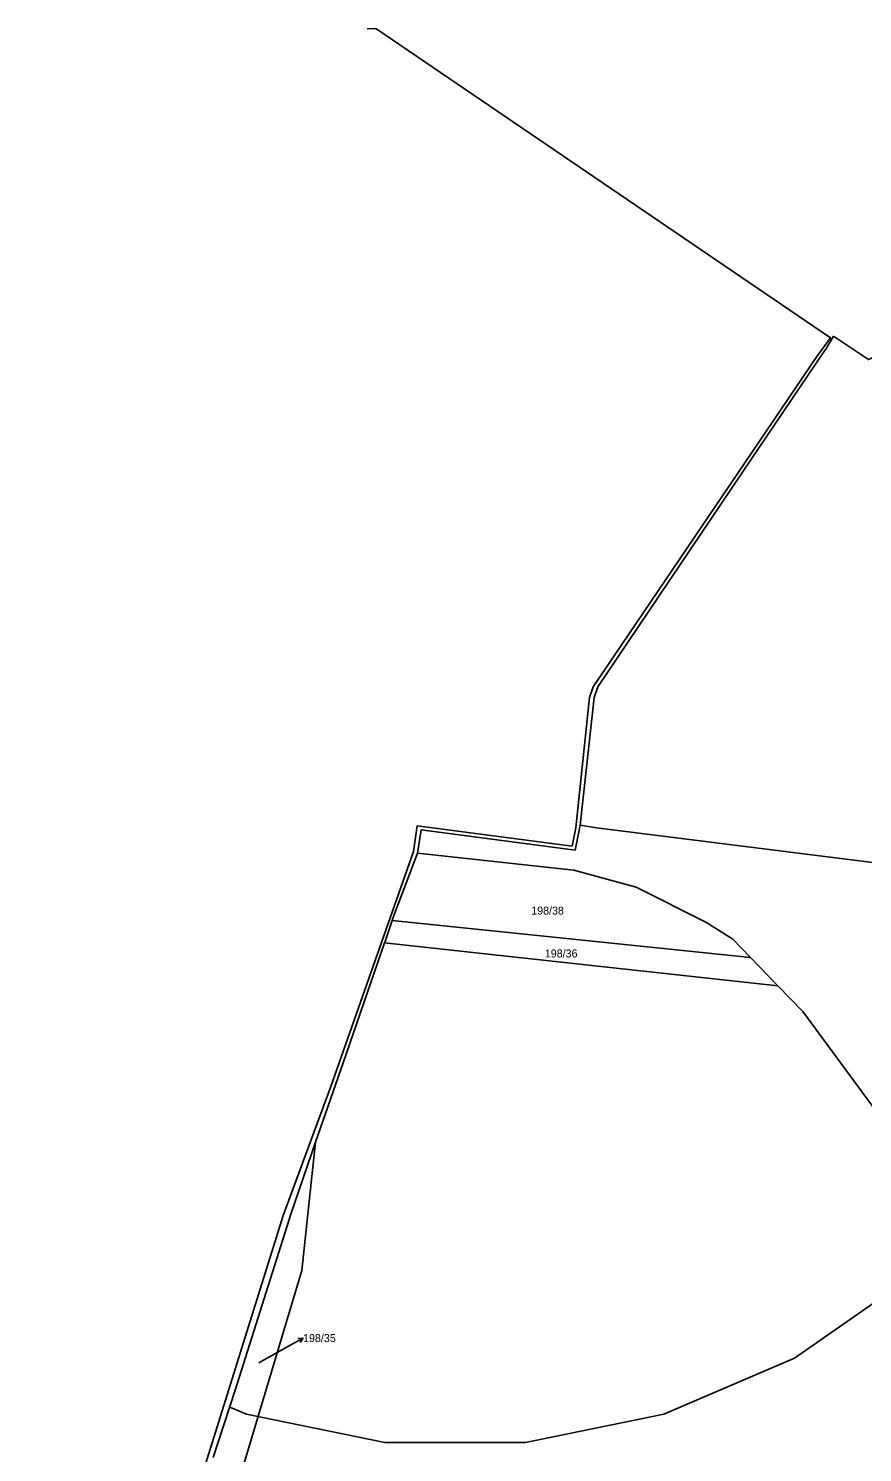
# Model space of a CAD drawing. Extents: x -882150 to -879379, y -1022570 to -1019819.
# Drawn here: x -880661.6 to -880484.4, y -1020201.6 to -1019899.2 of the extents above; entities that cross this region are included whole.
import ezdxf

# ---------------------------------------------------------------- set-up
doc = ezdxf.new("R2010")
doc.units = 0
for name, color, linetype in [('Hranice parcel', 7, 'Continuous'), ('Parcelní čísla', 7, 'Continuous'), ('Pop  PČ popisy', 7, 'Continuous'), ('Vnitřní kresba', 7, 'Continuous')]:
    doc.layers.add(name, color=color, linetype=linetype)

msp = doc.modelspace()

# ---------------------------------------------------------------- linework, layer by layer
at = {"layer": 'Hranice parcel'}
for p, q in [((-880492.18, -1019967.31), (-880490.55, -1019964.56)), ((-880492.57, -1019967.89), (-880492.18, -1019967.31)), ((-880541.4, -1020041.3), (-880540.65, -1020039.03)), ((-880544.4, -1020068.4), (-880541.4, -1020041.3)), ((-880578.19, -1020069.39), (-880578.97, -1020074.33)), ((-880578.19, -1020069.39), (-880545.46, -1020073.69)), ((-880545.46, -1020073.69), (-880544.4, -1020068.4)), ((-880540.91, -1020069), (-880544.4, -1020068.4)), ((-880584.03, -1020087.77), (-880578.97, -1020074.33)), ((-880584.03, -1020087.77), (-880584.33, -1020088.63)), ((-880584.33, -1020088.63), (-880585.79, -1020092.88)), ((-880508.2, -1020096.48), (-880584.33, -1020088.63)), ((-880594.78, -1020118.91), (-880585.96, -1020093.38)), ((-880585.79, -1020092.88), (-880585.96, -1020093.38)), ((-880585.96, -1020093.38), (-880502.38, -1020102.49)), ((-880502.38, -1020102.49), (-880508.2, -1020096.48)), ((-880594.78, -1020118.91), (-880600.6, -1020135.76))]:
    msp.add_line(p, q, dxfattribs=at)
for points in [[(-880490.55, -1019964.56), (-880483.11, -1019969.52), (-880470.01, -1019963.68)], [(-880540.65, -1020039.03), (-880507.94, -1019990.63), (-880492.57, -1019967.89)], [(-880128.9, -1020103.08), (-880132.45, -1020109.03), (-880189.45, -1020107.84), (-880241.14, -1020104.11), (-880287.51, -1020101.32), (-880356.63, -1020091.22), (-880430.92, -1020082.98), (-880459.65, -1020079.14), (-880540.91, -1020069)], [(-880578.97, -1020074.33), (-880545.76, -1020077.97), (-880532.46, -1020081.54), (-880517.71, -1020089.02), (-880511.97, -1020092.58), (-880508.2, -1020096.48)], [(-880502.38, -1020102.49), (-880497.06, -1020107.99), (-880478.95, -1020132.59), (-880425.73, -1020148.42), (-880407.16, -1020151.31), (-880349.97, -1020150.48), (-880276.63, -1020134.84)], [(-880600.6, -1020135.76), (-880605.8, -1020150.8), (-880617.7, -1020188.4), (-880622.4, -1020202.7)], [(-880617.77, -1020210.48), (-880603.54, -1020163.01), (-880600.6, -1020135.76)]]:
    msp.add_lwpolyline(points, dxfattribs=at)
at = {"layer": 'Pop  PČ popisy'}
for p, q in [((-880612.68, -1020182.6), (-880605.9, -1020178.8)), ((-880605.9, -1020178.8), (-880603.275, -1020177.345)), ((-880603.275, -1020177.345), (-880604.394, -1020177.393)), ((-880603.275, -1020177.345), (-880603.908, -1020178.269))]:
    msp.add_line(p, q, dxfattribs=at)
at = {"layer": 'Vnitřní kresba'}
msp.add_line((-880615.29, -1020193.51), (-880618.87, -1020191.97), dxfattribs=at)
for points in [[(-880589.65, -1019899.31), (-880587.82, -1019899.21), (-880491.2, -1019964.9), (-880494.11, -1019968.89), (-880541.64, -1020039.06), (-880542.42, -1020041.28), (-880545.34, -1020068.96), (-880546.12, -1020072.86), (-880579.04, -1020068.57), (-880579.82, -1020074.03), (-880597.35, -1020123.93), (-880607.48, -1020151.31), (-880625.79, -1020209.79), (-880632.41, -1020229.67), (-880646.83, -1020271.39), (-880661.64, -1020304.91)], [(-880615.29, -1020193.51), (-880585.87, -1020199.54), (-880556.01, -1020199.53), (-880526.59, -1020193.5), (-880498.86, -1020181.6), (-880474.31, -1020164.53), (-880453.64, -1020142.82), (-880448.85, -1020151.39), (-880430.15, -1020174.89), (-880405.16, -1020191.79), (-880376.74, -1020200.57), (-880346.52, -1020200.57), (-880318.05, -1020191.93), (-880293.2, -1020174.89)]]:
    msp.add_lwpolyline(points, dxfattribs=at)

# ---------------------------------------------------------------- texts
at = {"layer": 'Parcelní čísla'}
for s, p in [('198/38', (-880554.79, -1020087.4)), ('198/36', (-880551.9, -1020096.5)), ('198/35', (-880603.28, -1020178.18))]:
    msp.add_text(s, height=1.7, dxfattribs=at).set_placement(p)

doc.saveas('drawing.dxf')
